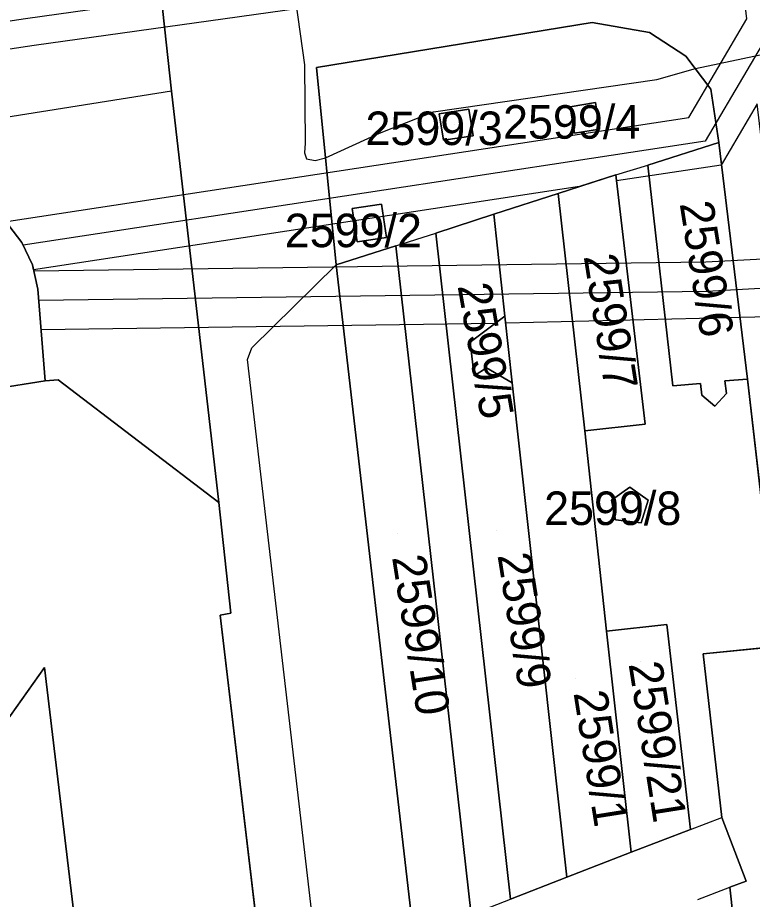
# Model space of a CAD drawing. Extents: x -263423 to -261326, y -1240067 to -1237864.
# Drawn here: x -263230.8 to -263187, y -1239760.6 to -1239708 of the extents above; entities that cross this region are included whole.
import ezdxf

# ---------------------------------------------------------------- set-up
doc = ezdxf.new("R2010")
doc.units = 0
for name, color, linetype in [('body_kn', 7, 'Continuous'), ('kladpar_druhypozemkov', 7, 'Continuous'), ('kladpar_hranice', 7, 'Continuous'), ('kladpar_parcelnecisla', 7, 'Continuous'), ('kladpar_plochy', 7, 'Continuous'), ('tarchy_linie', 7, 'Continuous'), ('zappar_hrandruhpozemk', 7, 'Continuous')]:
    doc.layers.add(name, color=color, linetype=linetype)

msp = doc.modelspace()

# ---------------------------------------------------------------- linework, layer by layer
at = {"layer": 'body_kn'}
for p, q in [((-263230.36, -1239708.08), (-263230.36, -1239708.08)), ((-263187.35, -1239708.08), (-263187.35, -1239708.08)), ((-263196.58, -1239708.3), (-263196.58, -1239708.3)), ((-263193.16, -1239708.89), (-263193.16, -1239708.89)), ((-263229.84, -1239709.68), (-263229.84, -1239709.68)), ((-263190.99, -1239710.3), (-263190.99, -1239710.3)), ((-263213.73, -1239710.83), (-263213.73, -1239710.83)), ((-263213.01, -1239710.98), (-263213.01, -1239710.98)), ((-263213.01, -1239710.98), (-263213.01, -1239710.98)), ((-263190.42, -1239711.05), (-263190.42, -1239711.05)), ((-263192.73, -1239711.7), (-263192.73, -1239711.7)), ((-263221.65, -1239712.39), (-263221.65, -1239712.39)), ((-263221.65, -1239712.39), (-263221.65, -1239712.39)), ((-263189.5, -1239712.27), (-263189.5, -1239712.27)), ((-263197.89, -1239713.32), (-263197.89, -1239713.32)), ((-263197.89, -1239713.32), (-263197.89, -1239713.32)), ((-263196.39, -1239713.08), (-263196.39, -1239713.08)), ((-263206.04, -1239713.63), (-263206.04, -1239713.63)), ((-263205.7, -1239713.75), (-263205.7, -1239713.75)), ((-263205.7, -1239713.75), (-263205.7, -1239713.75)), ((-263203.93, -1239713.47), (-263203.93, -1239713.47)), ((-263190.81, -1239713.96), (-263190.81, -1239713.96)), ((-263209.26, -1239714.91), (-263209.26, -1239714.91)), ((-263197.63, -1239714.91), (-263197.63, -1239714.91)), ((-263196.15, -1239714.66), (-263196.15, -1239714.66)), ((-263213.69, -1239715.49), (-263213.69, -1239715.49)), ((-263205.45, -1239715.32), (-263205.45, -1239715.32)), ((-263203.68, -1239715.05), (-263203.68, -1239715.05)), ((-263189.85, -1239715.38), (-263189.85, -1239715.38)), ((-263189.03, -1239715.46), (-263189.03, -1239715.46)), ((-263213.72, -1239716.07), (-263213.72, -1239716.07)), ((-263213.61, -1239716.44), (-263213.61, -1239716.44)), ((-263213.1, -1239716.53), (-263213.1, -1239716.53)), ((-263212.47, -1239716.38), (-263212.47, -1239716.38)), ((-263193.27, -1239716.81), (-263193.27, -1239716.81)), ((-263193.27, -1239716.81), (-263193.27, -1239716.81)), ((-263188.89, -1239716.8), (-263188.89, -1239716.8)), ((-263195.16, -1239717.38), (-263195.16, -1239717.38)), ((-263195.16, -1239717.39), (-263195.16, -1239717.39)), ((-263195.16, -1239717.39), (-263195.16, -1239717.39)), ((-263197.33, -1239718.09), (-263197.33, -1239718.09)), ((-263195.12, -1239717.75), (-263195.12, -1239717.75)), ((-263198.61, -1239718.5), (-263198.61, -1239718.5)), ((-263198.61, -1239718.5), (-263198.61, -1239718.5)), ((-263209.13, -1239719.14), (-263209.13, -1239719.14)), ((-263210.89, -1239719.4), (-263210.89, -1239719.4)), ((-263210.89, -1239719.4), (-263210.89, -1239719.4)), ((-263202.45, -1239719.74), (-263202.45, -1239719.74)), ((-263202.45, -1239719.74), (-263202.45, -1239719.74)), ((-263208.84, -1239721.12), (-263208.84, -1239721.12)), ((-263205.9, -1239720.86), (-263205.9, -1239720.86)), ((-263205.9, -1239720.86), (-263205.9, -1239720.86)), ((-263230.59, -1239721.42), (-263230.59, -1239721.42)), ((-263230.51, -1239721.58), (-263230.51, -1239721.58)), ((-263210.59, -1239721.38), (-263210.59, -1239721.38)), ((-263208.28, -1239721.62), (-263208.28, -1239721.62)), ((-263208.28, -1239721.62), (-263208.28, -1239721.62)), ((-263229.95, -1239722.75), (-263229.95, -1239722.75)), ((-263211.84, -1239722.75), (-263211.84, -1239722.75)), ((-263211.84, -1239722.75), (-263211.84, -1239722.75)), ((-263189.81, -1239722.58), (-263189.81, -1239722.58)), ((-263229.88, -1239723.06), (-263229.88, -1239723.06)), ((-263229.87, -1239723.12), (-263229.87, -1239723.12)), ((-263229.63, -1239724.21), (-263229.63, -1239724.21)), ((-263189.75, -1239724.34), (-263189.75, -1239724.34)), ((-263229.57, -1239724.88), (-263229.57, -1239724.88)), ((-263201.78, -1239725.82), (-263201.78, -1239725.82)), ((-263201.78, -1239725.82), (-263201.78, -1239725.82)), ((-263202.36, -1239726.25), (-263202.36, -1239726.25)), ((-263201.73, -1239726.24), (-263201.73, -1239726.24)), ((-263229.43, -1239726.62), (-263229.43, -1239726.62)), ((-263203.85, -1239727.37), (-263203.85, -1239727.37)), ((-263216.87, -1239727.7), (-263216.87, -1239727.7)), ((-263217.12, -1239728.4), (-263217.12, -1239728.4)), ((-263202.87, -1239728.9), (-263202.87, -1239728.9)), ((-263229.18, -1239729.68), (-263229.18, -1239729.68)), ((-263228.42, -1239729.61), (-263228.42, -1239729.61)), ((-263203.61, -1239729.38), (-263203.61, -1239729.38)), ((-263188.67, -1239729.68), (-263188.67, -1239729.68)), ((-263187.32, -1239729.58), (-263187.32, -1239729.58)), ((-263201.34, -1239729.78), (-263201.34, -1239729.78)), ((-263191.77, -1239729.97), (-263191.77, -1239729.97)), ((-263190.12, -1239729.82), (-263190.12, -1239729.82)), ((-263190.05, -1239730.53), (-263190.05, -1239730.53)), ((-263188.58, -1239730.43), (-263188.58, -1239730.43)), ((-263189.27, -1239731.18), (-263189.27, -1239731.18)), ((-263193.43, -1239732.25), (-263193.43, -1239732.25)), ((-263197.01, -1239732.65), (-263197.01, -1239732.65)), ((-263194.33, -1239736.02), (-263194.33, -1239736.02)), ((-263194.33, -1239736.02), (-263194.33, -1239736.02)), ((-263218.83, -1239736.92), (-263218.83, -1239736.92)), ((-263195.43, -1239736.78), (-263195.43, -1239736.78)), ((-263193.25, -1239736.78), (-263193.25, -1239736.78)), ((-263195.19, -1239737.97), (-263195.19, -1239737.97)), ((-263193.65, -1239738.14), (-263193.65, -1239738.14)), ((-263218.75, -1239743.65), (-263218.75, -1239743.65)), ((-263218.12, -1239743.53), (-263218.12, -1239743.53)), ((-263192.12, -1239744.2), (-263192.12, -1239744.2)), ((-263195.72, -1239744.61), (-263195.72, -1239744.61)), ((-263195.72, -1239744.61), (-263195.72, -1239744.61)), ((-263189.96, -1239745.96), (-263189.96, -1239745.96)), ((-263189.96, -1239745.96), (-263189.96, -1239745.96)), ((-263229.23, -1239746.77), (-263229.23, -1239746.77)), ((-263188.84, -1239755.71), (-263188.84, -1239755.71)), ((-263190.71, -1239756.43), (-263190.71, -1239756.43)), ((-263190.71, -1239756.43), (-263190.71, -1239756.43)), ((-263194.25, -1239757.78), (-263194.25, -1239757.78)), ((-263198.09, -1239759.28), (-263198.09, -1239759.28)), ((-263187.4, -1239759.5), (-263187.4, -1239759.5)), ((-263188.38, -1239759.87), (-263188.38, -1239759.87)), ((-263201.44, -1239760.59), (-263201.44, -1239760.59))]:
    msp.add_line(p, q, dxfattribs=at)
at = {"layer": 'kladpar_druhypozemkov'}
for p, q in [((-263197.09, -1239713.86), (-263197.09, -1239713.86)), ((-263204.81, -1239714.36), (-263204.81, -1239714.36)), ((-263191, -1239719.32), (-263191, -1239719.32)), ((-263209.83, -1239720.33), (-263209.83, -1239720.33)), ((-263196.34, -1239722.65), (-263196.34, -1239722.65)), ((-263202.26, -1239728.62), (-263202.26, -1239728.62)), ((-263194.37, -1239736.94), (-263194.37, -1239736.94)), ((-263202.26, -1239738.62), (-263202.26, -1239738.62)), ((-263208.21, -1239738.8), (-263208.21, -1239738.8)), ((-263193.67, -1239746.43), (-263193.67, -1239746.43)), ((-263197.58, -1239747.45), (-263197.58, -1239747.45))]:
    msp.add_line(p, q, dxfattribs=at)
at = {"layer": 'kladpar_hranice'}
msp.add_line((-263193.27, -1239716.81), (-263191.77, -1239729.97), dxfattribs=at)
for points in [[(-263242.87, -1239702.17), (-263223.13, -1239699.36), (-263222.81, -1239701.59), (-263222.81, -1239701.78), (-263221.65, -1239712.39), (-263218.83, -1239736.92), (-263228.42, -1239729.61), (-263229.18, -1239729.68), (-263229.63, -1239724.21), (-263229.95, -1239722.75), (-263230.59, -1239721.42), (-263231.35, -1239720.4)], [(-263207.6, -1239832.39), (-263207.79, -1239830.68), (-263209.14, -1239819.61), (-263209.97, -1239813.06), (-263210.6, -1239813.06), (-263213.04, -1239791.89), (-263212.47, -1239791.83), (-263213.56, -1239782.87), (-263212.99, -1239782.74), (-263214.15, -1239772.51), (-263214.72, -1239772.51), (-263215.68, -1239764.31), (-263216.32, -1239764.31), (-263218.75, -1239743.65), (-263218.12, -1239743.53), (-263218.83, -1239736.92), (-263221.65, -1239712.39), (-263222.81, -1239701.78), (-263222.81, -1239701.59), (-263223.13, -1239699.36)], [(-263213.01, -1239710.98), (-263196.58, -1239708.3), (-263193.16, -1239708.89), (-263190.99, -1239710.3), (-263189.5, -1239712.27), (-263189.03, -1239715.46), (-263193.27, -1239716.81)], [(-263213.01, -1239710.98), (-263211.84, -1239722.75), (-263207.22, -1239762.86), (-263206.76, -1239767.06), (-263203.53, -1239795.77), (-263203.04, -1239800.21), (-263200.39, -1239825.1), (-263199.75, -1239830.36), (-263199.25, -1239831.59), (-263197.88, -1239832.17), (-263179.25, -1239831.23), (-263177.12, -1239830.03), (-263176.6, -1239828.14), (-263176.8, -1239825.35), (-263185.49, -1239745.51), (-263187.32, -1239729.58), (-263189.03, -1239715.46), (-263189.5, -1239712.27), (-263190.99, -1239710.3), (-263193.16, -1239708.89), (-263196.58, -1239708.3), (-263213.01, -1239710.98)], [(-263203.79, -1239761.5), (-263208.28, -1239721.62), (-263211.84, -1239722.75), (-263213.01, -1239710.98)], [(-263196.15, -1239714.66), (-263196.39, -1239713.08), (-263197.89, -1239713.32), (-263197.63, -1239714.91), (-263196.15, -1239714.66)], [(-263197.89, -1239713.32), (-263196.39, -1239713.08), (-263196.15, -1239714.66), (-263197.63, -1239714.91), (-263197.89, -1239713.32)], [(-263203.68, -1239715.05), (-263203.93, -1239713.47), (-263205.7, -1239713.75), (-263205.45, -1239715.32), (-263203.68, -1239715.05)], [(-263205.7, -1239713.75), (-263203.93, -1239713.47), (-263203.68, -1239715.05), (-263205.45, -1239715.32), (-263205.7, -1239713.75)], [(-263193.27, -1239716.81), (-263189.03, -1239715.46), (-263187.32, -1239729.58), (-263188.67, -1239729.68), (-263188.58, -1239730.43), (-263189.27, -1239731.18), (-263190.05, -1239730.53), (-263190.12, -1239729.82), (-263191.77, -1239729.97), (-263193.27, -1239716.81)], [(-263201.44, -1239760.59), (-263198.09, -1239759.28), (-263194.25, -1239757.78), (-263190.71, -1239756.43), (-263192.12, -1239744.2), (-263195.72, -1239744.61), (-263197.01, -1239732.65), (-263193.43, -1239732.25), (-263195.16, -1239717.39), (-263198.61, -1239718.5), (-263202.45, -1239719.74), (-263205.9, -1239720.86), (-263201.44, -1239760.59)], [(-263198.61, -1239718.5), (-263195.16, -1239717.39), (-263193.43, -1239732.25), (-263197.01, -1239732.65), (-263198.61, -1239718.5)], [(-263202.45, -1239719.74), (-263198.61, -1239718.5), (-263197.01, -1239732.65), (-263195.72, -1239744.61), (-263194.25, -1239757.78), (-263198.09, -1239759.28), (-263201.34, -1239729.78), (-263201.78, -1239725.82), (-263202.45, -1239719.74)], [(-263208.84, -1239721.12), (-263209.13, -1239719.14), (-263210.89, -1239719.4), (-263210.59, -1239721.38), (-263208.84, -1239721.12)], [(-263210.89, -1239719.4), (-263209.13, -1239719.14), (-263208.84, -1239721.12), (-263210.59, -1239721.38), (-263210.89, -1239719.4)], [(-263205.9, -1239720.86), (-263202.45, -1239719.74), (-263201.78, -1239725.82), (-263203.85, -1239727.37), (-263203.61, -1239729.38), (-263202.87, -1239728.9), (-263201.34, -1239729.78), (-263198.09, -1239759.28), (-263201.44, -1239760.59), (-263205.9, -1239720.86)], [(-263231.35, -1239720.4), (-263230.59, -1239721.42), (-263229.95, -1239722.75), (-263229.63, -1239724.21), (-263229.18, -1239729.68), (-263235.21, -1239730.63)], [(-263211.84, -1239722.75), (-263208.28, -1239721.62), (-263203.79, -1239761.5), (-263207.22, -1239762.86), (-263211.84, -1239722.75)], [(-263201.78, -1239725.82), (-263201.34, -1239729.78), (-263202.87, -1239728.9), (-263203.61, -1239729.38), (-263203.85, -1239727.37), (-263201.78, -1239725.82)], [(-263235.21, -1239730.63), (-263229.18, -1239729.68), (-263228.42, -1239729.61), (-263218.83, -1239736.92), (-263218.12, -1239743.53), (-263218.75, -1239743.65), (-263216.32, -1239764.31), (-263215.68, -1239764.31), (-263214.72, -1239772.51), (-263214.15, -1239772.51), (-263212.99, -1239782.74), (-263213.56, -1239782.87), (-263212.47, -1239791.83), (-263213.04, -1239791.89), (-263223.77, -1239792.47), (-263224.86, -1239783.83), (-263229.88, -1239784.59), (-263230.26, -1239782.05), (-263231.79, -1239782.31)], [(-263191.77, -1239729.97), (-263190.12, -1239729.82), (-263190.05, -1239730.53), (-263189.27, -1239731.18), (-263188.58, -1239730.43), (-263188.67, -1239729.68), (-263187.32, -1239729.58), (-263185.49, -1239745.51), (-263189.96, -1239745.96), (-263188.84, -1239755.71), (-263187.4, -1239759.5), (-263188.38, -1239759.87), (-263185.63, -1239784.86), (-263183.51, -1239788.33), (-263185.16, -1239789.33), (-263181.2, -1239825.31), (-263176.8, -1239825.35), (-263176.6, -1239828.14), (-263177.12, -1239830.03), (-263179.25, -1239831.23), (-263197.88, -1239832.17), (-263199.25, -1239831.59), (-263199.75, -1239830.36), (-263200.39, -1239825.1)], [(-263194.33, -1239736.02), (-263195.43, -1239736.78), (-263195.19, -1239737.97), (-263193.65, -1239738.14), (-263193.25, -1239736.78), (-263194.33, -1239736.02)], [(-263194.33, -1239736.02), (-263193.25, -1239736.78), (-263193.65, -1239738.14), (-263195.19, -1239737.97), (-263195.43, -1239736.78), (-263194.33, -1239736.02)], [(-263195.72, -1239744.61), (-263192.12, -1239744.2), (-263190.71, -1239756.43), (-263194.25, -1239757.78), (-263195.72, -1239744.61)], [(-263189.96, -1239745.96), (-263185.49, -1239745.51), (-263176.8, -1239825.35), (-263181.2, -1239825.31), (-263185.16, -1239789.33), (-263183.51, -1239788.33), (-263185.63, -1239784.86), (-263188.38, -1239759.87), (-263187.4, -1239759.5), (-263188.84, -1239755.71), (-263189.96, -1239745.96)], [(-263231.95, -1239750.59), (-263229.23, -1239746.77), (-263225.89, -1239774.74), (-263231.03, -1239775.76), (-263230.78, -1239777.92), (-263232.3, -1239778.3)], [(-263232.3, -1239778.3), (-263230.78, -1239777.92), (-263231.03, -1239775.76), (-263225.89, -1239774.74), (-263229.23, -1239746.77), (-263231.95, -1239750.59)]]:
    msp.add_lwpolyline(points, dxfattribs=at)
at = {"layer": 'kladpar_plochy'}
for p, q in [((-263221.65, -1239712.39), (-263222.81, -1239701.78)), ((-263213.01, -1239710.98), (-263196.58, -1239708.3)), ((-263196.58, -1239708.3), (-263213.01, -1239710.98)), ((-263196.58, -1239708.3), (-263193.16, -1239708.89)), ((-263193.16, -1239708.89), (-263196.58, -1239708.3)), ((-263193.16, -1239708.89), (-263190.99, -1239710.3)), ((-263190.99, -1239710.3), (-263193.16, -1239708.89)), ((-263190.99, -1239710.3), (-263189.5, -1239712.27)), ((-263189.5, -1239712.27), (-263190.99, -1239710.3)), ((-263211.84, -1239722.75), (-263213.01, -1239710.98)), ((-263213.01, -1239710.98), (-263211.84, -1239722.75)), ((-263218.83, -1239736.92), (-263221.65, -1239712.39)), ((-263189.5, -1239712.27), (-263189.03, -1239715.46)), ((-263189.03, -1239715.46), (-263189.5, -1239712.27)), ((-263196.39, -1239713.08), (-263197.89, -1239713.32)), ((-263197.89, -1239713.32), (-263197.63, -1239714.91)), ((-263196.15, -1239714.66), (-263196.39, -1239713.08)), ((-263203.93, -1239713.47), (-263205.7, -1239713.75)), ((-263205.7, -1239713.75), (-263205.45, -1239715.32)), ((-263203.68, -1239715.05), (-263203.93, -1239713.47)), ((-263197.63, -1239714.91), (-263196.15, -1239714.66)), ((-263205.45, -1239715.32), (-263203.68, -1239715.05)), ((-263189.03, -1239715.46), (-263193.27, -1239716.81)), ((-263187.32, -1239729.58), (-263189.03, -1239715.46)), ((-263193.27, -1239716.81), (-263191.77, -1239729.97)), ((-263195.16, -1239717.39), (-263198.61, -1239718.5)), ((-263193.43, -1239732.25), (-263195.16, -1239717.39)), ((-263198.61, -1239718.5), (-263202.45, -1239719.74)), ((-263209.13, -1239719.14), (-263210.89, -1239719.4)), ((-263208.84, -1239721.12), (-263209.13, -1239719.14)), ((-263210.89, -1239719.4), (-263210.59, -1239721.38)), ((-263202.45, -1239719.74), (-263205.9, -1239720.86)), ((-263210.59, -1239721.38), (-263208.84, -1239721.12)), ((-263205.9, -1239720.86), (-263201.44, -1239760.59)), ((-263208.28, -1239721.62), (-263211.84, -1239722.75)), ((-263203.79, -1239761.5), (-263208.28, -1239721.62)), ((-263211.84, -1239722.75), (-263207.22, -1239762.86)), ((-263188.67, -1239729.68), (-263187.32, -1239729.58)), ((-263188.58, -1239730.43), (-263188.67, -1239729.68)), ((-263187.32, -1239729.58), (-263185.49, -1239745.51)), ((-263185.49, -1239745.51), (-263187.32, -1239729.58)), ((-263191.77, -1239729.97), (-263190.12, -1239729.82)), ((-263190.12, -1239729.82), (-263190.05, -1239730.53)), ((-263190.05, -1239730.53), (-263189.27, -1239731.18)), ((-263189.27, -1239731.18), (-263188.58, -1239730.43)), ((-263197.01, -1239732.65), (-263193.43, -1239732.25)), ((-263195.72, -1239744.61), (-263197.01, -1239732.65)), ((-263194.33, -1239736.02), (-263195.43, -1239736.78)), ((-263193.25, -1239736.78), (-263194.33, -1239736.02)), ((-263218.12, -1239743.53), (-263218.83, -1239736.92)), ((-263195.43, -1239736.78), (-263195.19, -1239737.97)), ((-263193.65, -1239738.14), (-263193.25, -1239736.78)), ((-263195.19, -1239737.97), (-263193.65, -1239738.14)), ((-263218.75, -1239743.65), (-263218.12, -1239743.53)), ((-263216.32, -1239764.31), (-263218.75, -1239743.65)), ((-263192.12, -1239744.2), (-263195.72, -1239744.61)), ((-263190.71, -1239756.43), (-263192.12, -1239744.2)), ((-263185.49, -1239745.51), (-263189.96, -1239745.96)), ((-263189.96, -1239745.96), (-263188.84, -1239755.71)), ((-263188.84, -1239755.71), (-263187.4, -1239759.5)), ((-263194.25, -1239757.78), (-263190.71, -1239756.43)), ((-263198.09, -1239759.28), (-263194.25, -1239757.78)), ((-263201.44, -1239760.59), (-263198.09, -1239759.28)), ((-263187.4, -1239759.5), (-263188.38, -1239759.87)), ((-263188.38, -1239759.87), (-263185.63, -1239784.86))]:
    msp.add_line(p, q, dxfattribs=at)
for points in [[(-263242.87, -1239702.17), (-263223.13, -1239699.36), (-263222.81, -1239701.59), (-263222.81, -1239701.78), (-263221.65, -1239712.39), (-263218.83, -1239736.92), (-263228.42, -1239729.61), (-263229.18, -1239729.68), (-263229.63, -1239724.21), (-263229.95, -1239722.75), (-263230.59, -1239721.42), (-263231.35, -1239720.4)], [(-263231.35, -1239720.4), (-263230.59, -1239721.42), (-263229.95, -1239722.75), (-263229.63, -1239724.21), (-263229.18, -1239729.68), (-263235.21, -1239730.63)], [(-263235.21, -1239730.63), (-263229.18, -1239729.68), (-263228.42, -1239729.61), (-263218.83, -1239736.92), (-263218.12, -1239743.53), (-263218.75, -1239743.65), (-263216.32, -1239764.31), (-263215.68, -1239764.31), (-263214.72, -1239772.51), (-263214.15, -1239772.51), (-263212.99, -1239782.74), (-263213.56, -1239782.87), (-263212.47, -1239791.83), (-263213.04, -1239791.89), (-263223.77, -1239792.47), (-263224.86, -1239783.83), (-263229.88, -1239784.59), (-263230.26, -1239782.05), (-263231.79, -1239782.31)], [(-263231.95, -1239750.59), (-263229.23, -1239746.77), (-263225.89, -1239774.74), (-263231.03, -1239775.76), (-263230.78, -1239777.92), (-263232.3, -1239778.3)], [(-263232.3, -1239778.3), (-263230.78, -1239777.92), (-263231.03, -1239775.76), (-263225.89, -1239774.74), (-263229.23, -1239746.77), (-263231.95, -1239750.59)]]:
    msp.add_lwpolyline(points, dxfattribs=at)
for points in [[(-263197.89, -1239713.32), (-263196.39, -1239713.08), (-263196.15, -1239714.66), (-263197.63, -1239714.91)], [(-263205.7, -1239713.75), (-263203.93, -1239713.47), (-263203.68, -1239715.05), (-263205.45, -1239715.32)], [(-263193.27, -1239716.81), (-263189.03, -1239715.46), (-263187.32, -1239729.58), (-263188.67, -1239729.68), (-263188.58, -1239730.43), (-263189.27, -1239731.18), (-263190.05, -1239730.53), (-263190.12, -1239729.82), (-263191.77, -1239729.97)], [(-263198.61, -1239718.5), (-263195.16, -1239717.39), (-263193.43, -1239732.25), (-263197.01, -1239732.65)], [(-263202.45, -1239719.74), (-263198.61, -1239718.5), (-263197.01, -1239732.65), (-263195.72, -1239744.61), (-263194.25, -1239757.78), (-263198.09, -1239759.28), (-263201.34, -1239729.78), (-263201.78, -1239725.82)], [(-263210.89, -1239719.4), (-263209.13, -1239719.14), (-263208.84, -1239721.12), (-263210.59, -1239721.38)], [(-263205.9, -1239720.86), (-263202.45, -1239719.74), (-263201.78, -1239725.82), (-263203.85, -1239727.37), (-263203.61, -1239729.38), (-263202.87, -1239728.9), (-263201.34, -1239729.78), (-263198.09, -1239759.28), (-263201.44, -1239760.59)], [(-263211.84, -1239722.75), (-263208.28, -1239721.62), (-263203.79, -1239761.5), (-263207.22, -1239762.86)], [(-263201.78, -1239725.82), (-263201.34, -1239729.78), (-263202.87, -1239728.9), (-263203.61, -1239729.38), (-263203.85, -1239727.37)], [(-263194.33, -1239736.02), (-263193.25, -1239736.78), (-263193.65, -1239738.14), (-263195.19, -1239737.97), (-263195.43, -1239736.78)], [(-263195.72, -1239744.61), (-263192.12, -1239744.2), (-263190.71, -1239756.43), (-263194.25, -1239757.78)], [(-263189.96, -1239745.96), (-263185.49, -1239745.51), (-263176.8, -1239825.35), (-263181.2, -1239825.31), (-263185.16, -1239789.33), (-263183.51, -1239788.33), (-263185.63, -1239784.86), (-263188.38, -1239759.87), (-263187.4, -1239759.5), (-263188.84, -1239755.71)]]:
    msp.add_lwpolyline(points, close=True, dxfattribs=at)
at = {"layer": 'tarchy_linie'}
for points in [[(-263224.19, -1239691.23), (-263217.93, -1239690.05), (-263217.18, -1239690.2), (-263216.5, -1239691.44), (-263216.29, -1239692.69), (-263215.81, -1239696.48), (-263215.12, -1239701.56), (-263214.52, -1239705.12), (-263213.73, -1239710.83), (-263213.69, -1239715.49), (-263213.72, -1239716.07), (-263213.61, -1239716.44), (-263213.1, -1239716.53), (-263212.47, -1239716.38), (-263209.26, -1239714.91), (-263206.04, -1239713.63), (-263192.73, -1239711.7), (-263190.42, -1239711.05), (-263183.74, -1239709.64), (-263176.98, -1239707.99), (-263175.58, -1239708.16), (-263173.72, -1239708.94)], [(-263185.2, -1239701.74), (-263230.36, -1239708.08), (-263276.2, -1239715), (-263322.22, -1239722), (-263350.78, -1239726.36)], [(-263182.4, -1239702.72), (-263189.85, -1239715.38), (-263230.51, -1239721.58)], [(-263231.61, -1239720.18), (-263190.81, -1239713.96), (-263187.35, -1239708.08), (-263187.86, -1239703.78), (-263229.84, -1239709.68), (-263275.95, -1239716.62)], [(-263172.53, -1239837.66), (-263180.03, -1239769.62), (-263185.24, -1239725.84), (-263201.73, -1239726.24), (-263201.78, -1239725.82), (-263202.36, -1239726.25), (-263229.43, -1239726.62), (-263229.57, -1239724.88), (-263229.63, -1239724.21), (-263229.87, -1239723.12), (-263189.81, -1239722.58), (-263185.65, -1239722.36), (-263186.74, -1239713.16), (-263188.89, -1239716.8), (-263195.12, -1239717.75), (-263195.16, -1239717.38), (-263197.33, -1239718.09), (-263229.88, -1239723.06), (-263229.95, -1239722.75), (-263230.51, -1239721.58), (-263230.59, -1239721.42), (-263231.35, -1239720.4)], [(-263177.35, -1239723.64), (-263189.75, -1239724.34), (-263229.57, -1239724.88)]]:
    msp.add_lwpolyline(points, dxfattribs=at)
at = {"layer": 'zappar_hrandruhpozemk'}
for p, q in [((-263221.65, -1239712.39), (-263298.33, -1239724.57)), ((-263195.16, -1239717.39), (-263193.27, -1239716.81)), ((-263208.28, -1239721.62), (-263205.9, -1239720.86)), ((-263190.71, -1239756.43), (-263188.84, -1239755.71)), ((-263190.28, -1239760.6), (-263188.38, -1239759.87)), ((-263203.79, -1239761.5), (-263201.44, -1239760.59))]:
    msp.add_line(p, q, dxfattribs=at)
msp.add_lwpolyline([(-263212.05, -1239772), (-263217.12, -1239728.4), (-263216.87, -1239727.7), (-263211.84, -1239722.75)], dxfattribs=at)

# ---------------------------------------------------------------- texts
at = {"layer": 'kladpar_parcelnecisla'}
for s, p in [('2599/4', (-263201.892, -1239715.23)), ('2599/3', (-263210.094, -1239715.61)), ('2599/2', (-263214.908, -1239721.7)), ('2599/8', (-263199.445, -1239738.27))]:
    msp.add_text(s, height=2, dxfattribs=at).set_placement(p)
for s, rotation, p in [('2599/6', 279, (-263191.369, -1239719.096)), ('2599/7', 279, (-263197.091, -1239722.243)), ('2599/5', 280, (-263204.611, -1239724.003)), ('2599/10', 279, (-263208.516, -1239740.189)), ('2599/9', 279, (-263202.229, -1239740.066)), ('2599/21', 279, (-263194.415, -1239746.554)), ('2599/1', 279, (-263197.695, -1239748.281))]:
    msp.add_text(s, height=2, rotation=rotation, dxfattribs=at).set_placement(p)

doc.saveas('drawing.dxf')
